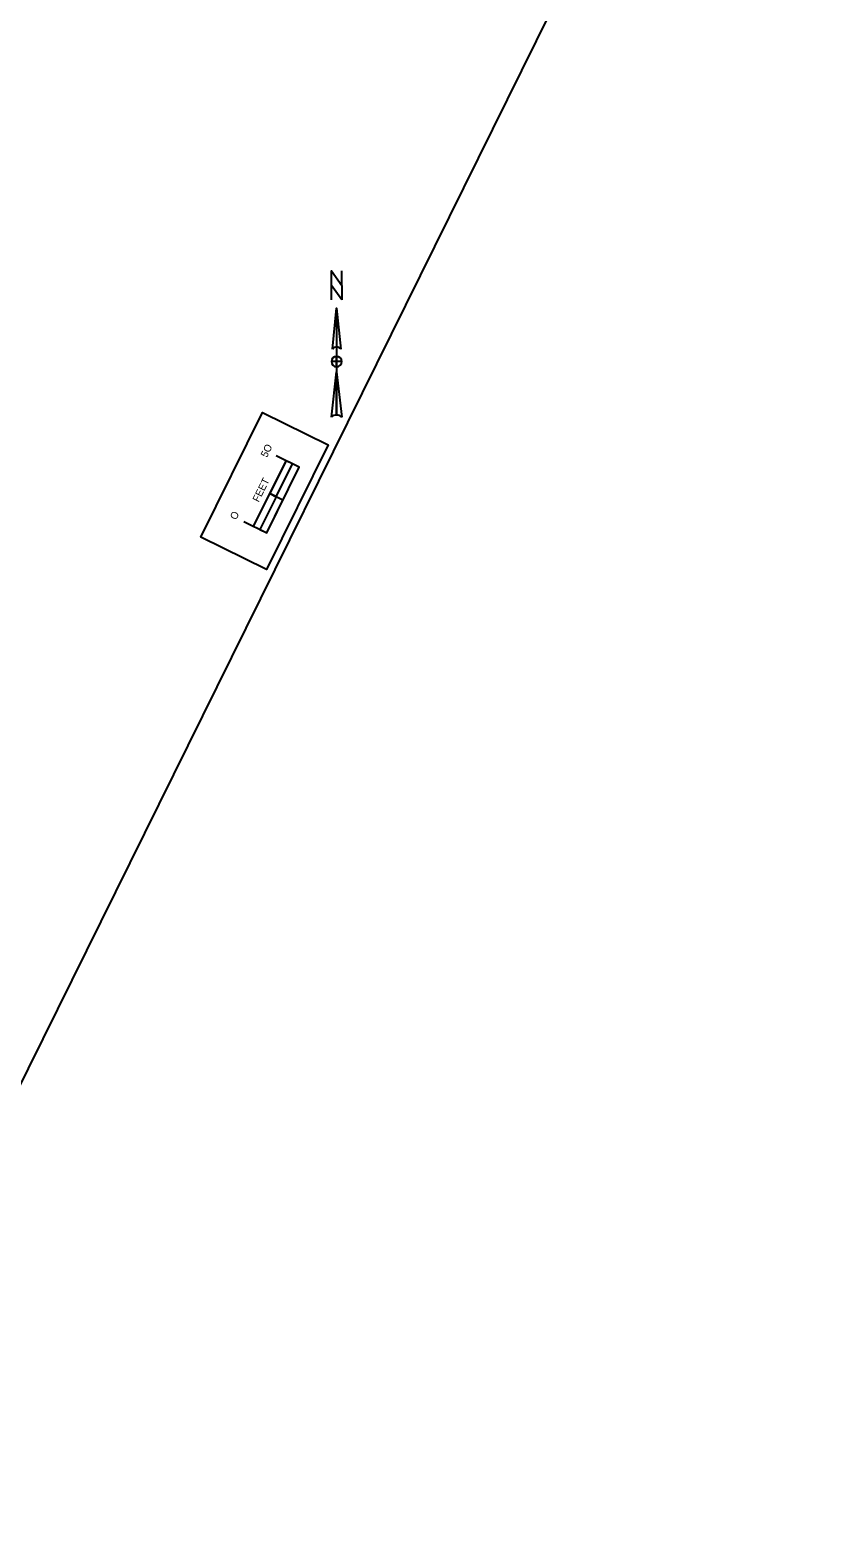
# Model space of a CAD drawing. Extents: x 14104283 to 14128447, y 8633203 to 8671666.
# Drawn here: x 14119697 to 14120232, y 8668497 to 8669528 of the extents above; entities that cross this region are included whole.
import ezdxf

# ---------------------------------------------------------------- set-up
doc = ezdxf.new("R2010")
doc.units = 0
for name, color, linetype in [('dsnCellsNorthArrow', 7, 'Continuous'), ('dsnCellsScaleBlock', 7, 'Continuous'), ('dsnNonPlotable', 7, 'Continuous')]:
    doc.layers.add(name, color=color, linetype=linetype)

msp = doc.modelspace()

# ---------------------------------------------------------------- linework, layer by layer
at = {"layer": 'dsnCellsNorthArrow'}
for p, q in [((14119906.8, 8669338.4), (14119909.6, 8669310.3)), ((14119906.8, 8669338.4), (14119906.8, 8669265.2)), ((14119904, 8669310.3), (14119904, 8669310.3)), ((14119904.1, 8669310.5), (14119904.6, 8669311.1)), ((14119903.3, 8669263.8), (14119906.8, 8669294.8)), ((14119906.8, 8669298.3), (14119906.8, 8669298.3))]:
    msp.add_line(p, q, dxfattribs=at)
msp.add_lwpolyline([(14119910.3, 8669344.1), (14119903.3, 8669353.9), (14119903.3, 8669363.8), (14119910.3, 8669353.9)], close=True, dxfattribs=at)
for points in [[(14119903.3, 8669344.1), (14119903.3, 8669363.8), (14119910.3, 8669353.9), (14119910.3, 8669363.8)], [(14119904, 8669310.3), (14119906.8, 8669338.4), (14119906.8, 8669311.7)], [(14119906.8, 8669298.3), (14119906.8, 8669301.8), (14119903.3, 8669301.8)], [(14119910.3, 8669301.8), (14119906.8, 8669301.8), (14119906.8, 8669305.3)], [(14119906.8, 8669265.2), (14119906.8, 8669294.8), (14119910.3, 8669263.8)]]:
    msp.add_lwpolyline(points, dxfattribs=at)
for centre, radius, start, end in [((14119906.8, 8669308.2), 3.52, 90.0204, 143.1257), ((14119906.8, 8669308.2), 3.52, 36.8481, 90.0218), ((14119906.8, 8669301.8), 3.52, 90, 180), ((14119906.8, 8669301.8), 3.52, 180, 270), ((14119906.8, 8669301.8), 3.52, 0, 90), ((14119906.8, 8669301.8), 3.52, 270, 360), ((14119906.8, 8669260.1), 5.1, 89.9894, 133.619), ((14119906.8, 8669260.1), 5.11, 46.4021, 90.0006)]:
    msp.add_arc(centre, radius, start, end, dxfattribs=at)
at = {"layer": 'dsnCellsScaleBlock'}
msp.add_line((14119870, 8669207.1), (14119861.1, 8669211.5), dxfattribs=at)
msp.add_line((14119870, 8669207.1), (14119861.1, 8669211.5), dxfattribs=at)
for points in [[(14119814, 8669181.8), (14119856.1, 8669267), (14119901, 8669244.8), (14119858.8, 8669159.7)], [(14119858.8, 8669159.7), (14119814, 8669181.8), (14119856.1, 8669267), (14119901, 8669244.8)], [(14119865.5, 8669209.3), (14119876.6, 8669231.8), (14119872.2, 8669234), (14119861.1, 8669211.5)], [(14119859, 8669184.7), (14119870, 8669207.1), (14119865.5, 8669209.3), (14119854.4, 8669186.9)]]:
    msp.add_lwpolyline(points, close=True, dxfattribs=at)
for points in [[(14119843.3, 8669192.5), (14119859, 8669184.7), (14119881.1, 8669229.5), (14119865.4, 8669237.3)], [(14119850, 8669189.1), (14119872.2, 8669234)]]:
    msp.add_lwpolyline(points, dxfattribs=at)
at = {"layer": 'dsnNonPlotable'}
msp.add_lwpolyline([(14118631.6, 8668945.1), (14119326.4, 8670350.2), (14120231.7, 8669902.6), (14119537, 8668497.5)], close=True, dxfattribs=at)

# ---------------------------------------------------------------- texts
at = {"layer": 'dsnCellsScaleBlock'}
for s, p in [('5O', (14119859.1, 8669235.8)), ('FEET', (14119853.5, 8669205.3)), ('O', (14119838.1, 8669193.2))]:
    msp.add_text(s, height=5, rotation=63.6912, dxfattribs=at).set_placement(p)

doc.saveas('drawing.dxf')
